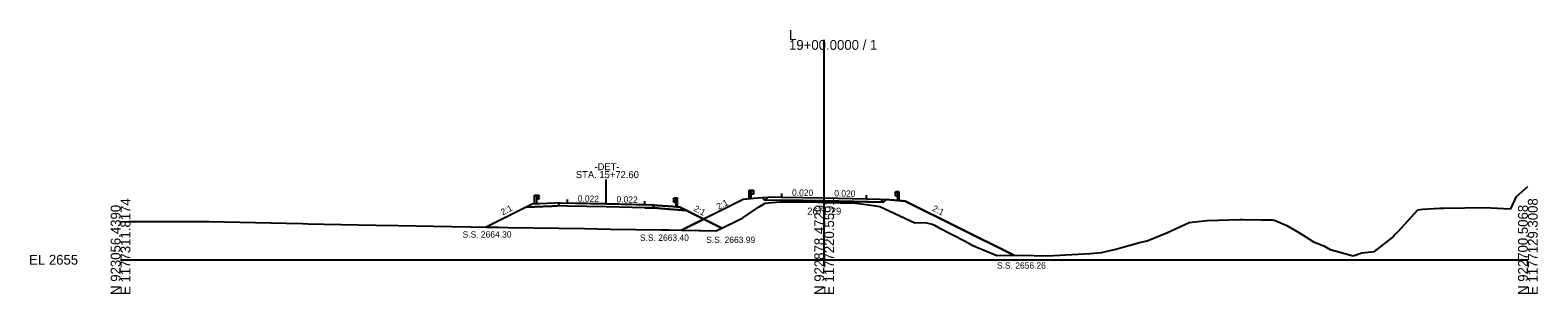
# Model space of a CAD drawing. Extents: x -26 to 1403, y -10 to 9563.
# Drawn here: x -25.7 to 402.8, y 8990.3 to 9065.3 of the extents above; entities that cross this region are included whole.
import ezdxf

# ---------------------------------------------------------------- set-up
doc = ezdxf.new("R2010")
doc.units = 0
for name, color, linetype in [('Exist Cross Section Cell', 7, 'Continuous'), ('Exist XS Center Line Elevation Label', 7, 'Continuous'), ('Exist XS Ground Line', 7, 'Continuous'), ('Prop XS Dump Level', 7, 'Continuous'), ('Prop XS Earthwork Shape', 7, 'Continuous'), ('Prop XS EOT Tick Mark', 7, 'Continuous'), ('Prop XS Finish Grade', 7, 'Continuous'), ('Prop XS Finish Grade Earthwork', 7, 'Continuous'), ('Prop XS Finish Grade Paved Shoulder', 7, 'Continuous'), ('Prop XS Finish Grade Pavement', 7, 'Continuous'), ('Prop XS Guardrail', 7, 'Continuous'), ('Prop XS Pvmt Edge Slope', 7, 'Continuous'), ('Prop XS SE Text', 7, 'Continuous'), ('Prop XS Shoulder Borrow Shape', 7, 'Continuous'), ('Prop XS Side Slope Text', 7, 'Continuous'), ('Prop XS SS Elevation Text', 7, 'Continuous'), ('Prop XS Subgrade Earthwork', 7, 'Continuous'), ('Prop XS Vertical Lines', 7, 'Continuous')]:
    doc.layers.add(name, color=color, linetype=linetype)

msp = doc.modelspace()

# ---------------------------------------------------------------- linework, layer by layer
at = {"layer": 'Exist Cross Section Cell'}
for p, q in [((200, 9000), (200, 9062.49)), ((0, 9000), (200, 9000)), ((200, 9000), (400, 9000))]:
    msp.add_line(p, q, dxfattribs=at)
at = {"layer": 'Exist XS Ground Line'}
for p, q in [((396.75, 9018.03), (400, 9020.83)), ((183.23, 9016.09), (187.42, 9016.46)), ((187.42, 9016.46), (187.88, 9016.46)), ((187.88, 9016.46), (198.23, 9016.34)), ((198.23, 9016.34), (200, 9016.29)), ((395.2, 9014.49), (396.75, 9018.03)), ((176.83, 9011.93), (181.34, 9014.91)), ((181.34, 9014.91), (183.23, 9016.09)), ((200, 9016.29), (208.98, 9016.08)), ((208.98, 9016.08), (209.49, 9016.07)), ((209.49, 9016.07), (209.85, 9016.03)), ((209.85, 9016.03), (213.89, 9015.39)), ((213.89, 9015.39), (215.77, 9015.1)), ((215.77, 9015.1), (225.72, 9010.54)), ((363.1, 9008.07), (368.74, 9014.2)), ((368.74, 9014.2), (370.13, 9014.34)), ((370.13, 9014.34), (374.96, 9014.69)), ((374.96, 9014.69), (376.25, 9014.69)), ((376.25, 9014.69), (387.91, 9014.87)), ((387.91, 9014.87), (393.12, 9014.62)), ((393.12, 9014.62), (395.2, 9014.49)), ((0, 9010.82), (2.35, 9010.84)), ((2.35, 9010.84), (25.16, 9010.84)), ((25.16, 9010.84), (47.07, 9010.38)), ((47.07, 9010.38), (51.76, 9010.29)), ((51.76, 9010.29), (53.28, 9010.25)), ((53.28, 9010.25), (57.87, 9010.15)), ((57.87, 9010.15), (72.53, 9009.82)), ((72.53, 9009.82), (78.97, 9009.77)), ((78.97, 9009.77), (88.99, 9009.54)), ((88.99, 9009.54), (104.69, 9009.29)), ((104.69, 9009.29), (107.42, 9009.25)), ((107.42, 9009.25), (110.11, 9009.19)), ((110.11, 9009.19), (131.88, 9008.86)), ((131.88, 9008.86), (139.35, 9008.72)), ((139.35, 9008.72), (153.53, 9008.52)), ((153.53, 9008.52), (154.29, 9008.49)), ((154.29, 9008.49), (155.91, 9008.47)), ((155.91, 9008.47), (169.32, 9008.2)), ((169.32, 9008.2), (174.98, 9010.98)), ((174.98, 9010.98), (176.83, 9011.93)), ((225.72, 9010.54), (228.63, 9010.62)), ((228.63, 9010.62), (230.3, 9010.21)), ((230.3, 9010.21), (230.67, 9010.13)), ((230.67, 9010.13), (231.34, 9009.81)), ((231.34, 9009.81), (232.49, 9009.17)), ((232.49, 9009.17), (240.07, 9005.26)), ((297.54, 9007.74), (303.71, 9010.63)), ((303.71, 9010.63), (308.86, 9011.15)), ((308.86, 9011.15), (318.09, 9011.47)), ((318.09, 9011.47), (318.56, 9011.47)), ((318.56, 9011.47), (319.13, 9011.47)), ((319.13, 9011.47), (324.12, 9011.38)), ((324.12, 9011.38), (327.32, 9011.32)), ((327.32, 9011.32), (327.78, 9011.28)), ((327.78, 9011.28), (328.18, 9011.19)), ((328.18, 9011.19), (331.48, 9009.7)), ((331.48, 9009.7), (334.47, 9008.05)), ((334.47, 9008.05), (336.1, 9006.95)), ((361.97, 9007.02), (363.1, 9008.07)), ((240.07, 9005.26), (242.29, 9004.02)), ((242.29, 9004.02), (244.01, 9003.28)), ((282.88, 9003.03), (289.64, 9004.95)), ((289.64, 9004.95), (291.76, 9005.39)), ((291.76, 9005.39), (297.54, 9007.74)), ((336.1, 9006.95), (339.06, 9005.12)), ((339.06, 9005.12), (341.97, 9004)), ((341.97, 9004), (343.8, 9002.94)), ((356.45, 9002.38), (361.52, 9006.3)), ((361.52, 9006.3), (361.97, 9007.02)), ((244.01, 9003.28), (244.96, 9002.94)), ((244.96, 9002.94), (249.04, 9001.21)), ((249.04, 9001.21), (255.75, 9001.28)), ((255.75, 9001.28), (263.45, 9001.09)), ((263.45, 9001.09), (275.58, 9001.77)), ((275.58, 9001.77), (278.78, 9002.06)), ((278.78, 9002.06), (282.88, 9003.03)), ((343.8, 9002.94), (350.31, 9001.14)), ((350.31, 9001.14), (352.82, 9001.96)), ((352.82, 9001.96), (356.45, 9002.38))]:
    msp.add_line(p, q, dxfattribs=at)
at = {"layer": 'Prop XS Dump Level'}
for p, q in [((188, 9017.81), (200, 9017.57)), ((200, 9017.57), (212, 9017.33)), ((125, 9016.15), (138, 9015.86)), ((138, 9015.86), (127, 9016.1)), ((149, 9015.62), (138, 9015.86)), ((138, 9015.86), (151, 9015.58))]:
    msp.add_line(p, q, dxfattribs=at)
at = {"layer": 'Prop XS Earthwork Shape'}
for p, q in [((177, 9017.17), (165.78, 9011.56)), ((182.43, 9017.6), (180, 9017.41)), ((183.15, 9016.88), (182.43, 9017.6)), ((188, 9016.97), (183.15, 9016.88)), ((183.23, 9016.09), (187.42, 9016.46)), ((187.42, 9016.46), (187.88, 9016.46)), ((187.88, 9016.46), (198.23, 9016.34)), ((200, 9016.73), (188, 9016.97)), ((198.23, 9016.34), (200, 9016.29)), ((200, 9016.29), (200, 9016.73)), ((216.85, 9016.4), (200, 9016.73)), ((200, 9016.73), (200, 9016.29)), ((217.57, 9017.12), (216.85, 9016.4)), ((220, 9016.93), (217.57, 9017.12)), ((220.82, 9016.86), (220, 9016.93)), ((253.86, 9001.26), (223, 9016.69)), ((115.3, 9014.99), (103.92, 9009.3)), ((122.61, 9015.27), (115.3, 9014.99)), ((124.18, 9015.33), (122.61, 9015.27)), ((127, 9015.27), (124.18, 9015.33)), ((138, 9015.03), (127, 9015.27)), ((149, 9014.79), (138, 9015.03)), ((151.85, 9014.73), (149, 9014.79)), ((153.43, 9014.6), (151.85, 9014.73)), ((160.87, 9014.01), (153.43, 9014.6)), ((165.78, 9011.56), (160.87, 9014.01)), ((176.83, 9011.93), (181.34, 9014.91)), ((181.34, 9014.91), (183.23, 9016.09)), ((200, 9016.29), (208.98, 9016.08)), ((208.98, 9016.08), (209.49, 9016.07)), ((209.49, 9016.07), (209.85, 9016.03)), ((209.85, 9016.03), (213.89, 9015.39)), ((213.89, 9015.39), (215.77, 9015.1)), ((215.77, 9015.1), (225.72, 9010.54)), ((103.92, 9009.3), (104.69, 9009.29)), ((104.69, 9009.29), (107.42, 9009.25)), ((107.42, 9009.25), (110.11, 9009.19)), ((110.11, 9009.19), (131.88, 9008.86)), ((131.88, 9008.86), (139.35, 9008.72)), ((139.35, 9008.72), (153.53, 9008.52)), ((153.53, 9008.52), (154.29, 9008.49)), ((154.29, 9008.49), (155.91, 9008.47)), ((155.91, 9008.47), (159.45, 9008.4)), ((159.45, 9008.4), (165.78, 9011.56)), ((165.78, 9011.56), (159.45, 9008.4)), ((165.78, 9011.56), (159.45, 9008.4)), ((159.45, 9008.4), (169.32, 9008.2)), ((159.45, 9008.4), (169.32, 9008.2)), ((170.92, 9008.98), (165.78, 9011.56)), ((170.92, 9008.98), (165.78, 9011.56)), ((165.78, 9011.56), (170.92, 9008.98)), ((169.32, 9008.2), (170.92, 9008.98)), ((169.32, 9008.2), (170.92, 9008.98)), ((170.92, 9008.98), (174.98, 9010.98)), ((174.98, 9010.98), (176.83, 9011.93)), ((225.72, 9010.54), (228.63, 9010.62)), ((228.63, 9010.62), (230.3, 9010.21)), ((230.3, 9010.21), (230.67, 9010.13)), ((230.67, 9010.13), (231.34, 9009.81)), ((231.34, 9009.81), (232.49, 9009.17)), ((232.49, 9009.17), (240.07, 9005.26)), ((240.07, 9005.26), (242.29, 9004.02)), ((242.29, 9004.02), (244.01, 9003.28)), ((244.01, 9003.28), (244.96, 9002.94)), ((244.96, 9002.94), (249.04, 9001.21)), ((249.04, 9001.21), (253.86, 9001.26))]:
    msp.add_line(p, q, dxfattribs=at)
for points in [[(180, 9017.41), (179.18, 9017.34), (178.68, 9017.3), (177, 9017.17)], [(223, 9016.69), (221.32, 9016.82), (220.82, 9016.86)]]:
    msp.add_lwpolyline(points, dxfattribs=at)
at = {"layer": 'Prop XS EOT Tick Mark'}
for p, q in [((127, 9016.1), (127, 9017.1)), ((149, 9015.62), (149, 9016.62)), ((188, 9017.81), (188, 9018.81)), ((212, 9017.33), (212, 9018.33))]:
    msp.add_line(p, q, dxfattribs=at)
at = {"layer": 'Prop XS Finish Grade'}
for p, q in [((184, 9017.73), (182.43, 9017.6)), ((216, 9017.25), (217.57, 9017.12)), ((125, 9016.15), (123.43, 9016.09)), ((151, 9015.58), (152.58, 9015.46))]:
    msp.add_line(p, q, dxfattribs=at)
at = {"layer": 'Prop XS Finish Grade Earthwork'}
for p, q in [((177, 9017.17), (159.45, 9008.4)), ((180, 9017.41), (177, 9017.17)), ((182.43, 9017.6), (180, 9017.41)), ((217.57, 9017.12), (220, 9016.93)), ((220, 9016.93), (223, 9016.69)), ((223, 9016.69), (253.86, 9001.26)), ((115.3, 9014.99), (103.92, 9009.3)), ((117, 9015.84), (115.3, 9014.99)), ((119, 9015.92), (117, 9015.84)), ((123.43, 9016.09), (119, 9015.92)), ((152.58, 9015.46), (157.01, 9015.1)), ((157.01, 9015.1), (159.01, 9014.94)), ((159.01, 9014.94), (160.87, 9014.01)), ((160.87, 9014.01), (170.92, 9008.98))]:
    msp.add_line(p, q, dxfattribs=at)
at = {"layer": 'Prop XS Finish Grade Paved Shoulder'}
for p, q in [((188, 9017.81), (184, 9017.73)), ((212, 9017.33), (216, 9017.25))]:
    msp.add_line(p, q, dxfattribs=at)
at = {"layer": 'Prop XS Finish Grade Pavement'}
for p, q in [((188, 9017.81), (200, 9017.57)), ((200, 9017.57), (212, 9017.33)), ((125, 9016.15), (138, 9015.86)), ((138, 9015.86), (151, 9015.58))]:
    msp.add_line(p, q, dxfattribs=at)
at = {"layer": 'Prop XS Guardrail'}
for p, q in [((117.68, 9018.37), (118.18, 9018.37)), ((117.68, 9015.87), (117.68, 9018.37)), ((118.18, 9018.37), (118.68, 9018.37)), ((118.18, 9018.37), (118.18, 9015.87)), ((118.68, 9017.23), (118.18, 9017.23)), ((118.68, 9018.37), (118.97, 9018.17)), ((118.97, 9018.05), (118.68, 9017.85)), ((118.68, 9017.85), (118.68, 9017.75)), ((118.68, 9017.75), (118.97, 9017.55)), ((118.97, 9017.43), (118.68, 9017.23)), ((118.97, 9018.17), (119, 9018.11)), ((119, 9018.11), (118.97, 9018.05)), ((118.97, 9017.55), (119, 9017.49)), ((119, 9017.49), (118.97, 9017.43)), ((157.03, 9017.3), (157, 9017.24)), ((157, 9017.24), (157.03, 9017.18)), ((157.03, 9016.68), (157, 9016.62)), ((157, 9016.62), (157.03, 9016.56)), ((157.32, 9017.5), (157.03, 9017.3)), ((157.03, 9017.18), (157.32, 9016.98)), ((157.32, 9016.88), (157.03, 9016.68)), ((157.03, 9016.56), (157.32, 9016.36)), ((157.82, 9017.5), (157.32, 9017.5)), ((157.32, 9016.98), (157.32, 9016.88)), ((157.32, 9016.36), (157.82, 9016.36)), ((158.32, 9017.5), (157.82, 9017.5)), ((157.82, 9017.5), (157.82, 9015)), ((158.32, 9015), (158.32, 9017.5)), ((178.68, 9019.8), (179.18, 9019.8)), ((178.68, 9017.3), (178.68, 9019.8)), ((179.18, 9019.8), (179.68, 9019.8)), ((179.18, 9019.8), (179.18, 9017.3)), ((179.68, 9018.67), (179.18, 9018.67)), ((179.68, 9019.8), (179.97, 9019.6)), ((179.97, 9019.48), (179.68, 9019.28)), ((179.68, 9019.28), (179.68, 9019.19)), ((179.68, 9019.19), (179.97, 9018.99)), ((179.97, 9018.87), (179.68, 9018.67)), ((179.97, 9019.6), (180, 9019.54)), ((180, 9019.54), (179.97, 9019.48)), ((179.97, 9018.99), (180, 9018.93)), ((180, 9018.93), (179.97, 9018.87)), ((220.03, 9019.12), (220, 9019.06)), ((220, 9019.06), (220.03, 9019)), ((220.03, 9018.51), (220, 9018.45)), ((220, 9018.45), (220.03, 9018.39)), ((220.32, 9019.32), (220.03, 9019.12)), ((220.03, 9019), (220.32, 9018.8)), ((220.32, 9018.71), (220.03, 9018.51)), ((220.03, 9018.39), (220.32, 9018.19)), ((220.82, 9019.32), (220.32, 9019.32)), ((220.32, 9018.8), (220.32, 9018.71)), ((220.32, 9018.19), (220.82, 9018.19)), ((221.32, 9019.32), (220.82, 9019.32)), ((220.82, 9019.32), (220.82, 9016.82)), ((221.32, 9016.82), (221.32, 9019.32))]:
    msp.add_line(p, q, dxfattribs=at)
at = {"layer": 'Prop XS Pvmt Edge Slope'}
for p, q in [((184, 9017.73), (183.15, 9016.88)), ((216, 9017.25), (216.85, 9016.4)), ((125, 9016.15), (124.18, 9015.33)), ((151, 9015.58), (151.85, 9014.73))]:
    msp.add_line(p, q, dxfattribs=at)
at = {"layer": 'Prop XS Shoulder Borrow Shape'}
for p, q in [((117, 9015.84), (115.3, 9014.99)), ((115.3, 9014.99), (122.61, 9015.27)), ((117.68, 9015.87), (117, 9015.84)), ((123.43, 9016.09), (119, 9015.92)), ((122.61, 9015.27), (124.18, 9015.33)), ((125, 9016.15), (123.43, 9016.09)), ((124.18, 9015.33), (125, 9016.15)), ((152.58, 9015.46), (151, 9015.58)), ((151, 9015.58), (151.85, 9014.73)), ((151.85, 9014.73), (153.43, 9014.6)), ((157.01, 9015.1), (152.58, 9015.46)), ((153.43, 9014.6), (160.87, 9014.01)), ((157.82, 9015.04), (157.01, 9015.1)), ((158.32, 9015), (157.82, 9015.04)), ((159.01, 9014.94), (158.32, 9015)), ((158.32, 9015), (158.32, 9015)), ((160.87, 9014.01), (159.01, 9014.94))]:
    msp.add_line(p, q, dxfattribs=at)
for points in [[(119, 9015.92), (118.18, 9015.88), (117.68, 9015.87)], [(158.32, 9015), (158.32, 9015)]]:
    msp.add_lwpolyline(points, dxfattribs=at)
at = {"layer": 'Prop XS Subgrade Earthwork'}
for p, q in [((183.15, 9016.88), (182.43, 9017.6)), ((188, 9016.97), (183.15, 9016.88)), ((188, 9016.96), (188, 9016.97)), ((188, 9016.97), (216.85, 9016.4)), ((216.85, 9016.4), (217.57, 9017.12)), ((122.61, 9015.27), (115.3, 9014.99)), ((124.18, 9015.33), (122.61, 9015.27)), ((127, 9015.27), (124.18, 9015.33)), ((138, 9015.03), (127, 9015.27)), ((149, 9014.79), (138, 9015.03)), ((149, 9014.79), (151.85, 9014.73)), ((151.85, 9014.73), (153.43, 9014.6)), ((153.43, 9014.6), (160.87, 9014.01))]:
    msp.add_line(p, q, dxfattribs=at)
at = {"layer": 'Prop XS Vertical Lines'}
msp.add_line((138, 9015.86), (138, 9022.86), dxfattribs=at)

# ---------------------------------------------------------------- texts
at = {"layer": 'Exist Cross Section Cell'}
for s, p in [('L', (190, 9062.49)), ('19+00.0000 / 1', (190, 9059.69)), ('EL 2655', (-26, 8998.6))]:
    msp.add_text(s, height=2.8, dxfattribs=at).set_placement(p)
for s, p in [('E 1177311.8174', (2.8, 8990)), ('E 1177220.5591', (202.8, 8990)), ('E 1177129.3008', (402.8, 8990)), ('N 923056.4390', (0, 8990)), ('N 922878.4729', (200, 8990)), ('N 922700.5068', (400, 8990))]:
    msp.add_text(s, height=2.8, rotation=90, dxfattribs=at).set_placement(p)
at = {"layer": 'Exist XS Center Line Elevation Label'}
msp.add_text('2671.29', height=2, dxfattribs=at).set_placement((195.18, 9012.83))
at = {"layer": 'Prop XS Dump Level'}
for s, p in [('Case2', (180, 9017.37)), ('Case2', (220, 9016.89)), ('Case1', (119, 9015.76)), ('Case1', (157, 9015.06))]:
    msp.add_text(s, height=0.04, dxfattribs=at).set_placement(p)
at = {"layer": 'Prop XS SE Text'}
for s, rotation, p in [('0.022', 358.756, (129.95, 9016.54)), ('0.022', 358.756, (140.95, 9016.3)), ('0.020', 358.8542, (190.84, 9018.25)), ('0.020', 358.8542, (202.84, 9018.01))]:
    msp.add_text(s, height=1.8, rotation=rotation, dxfattribs=at).set_placement(p)
at = {"layer": 'Prop XS Side Slope Text'}
for rotation, p in [(26.5651, (169.93, 9014.17)), (26.5651, (108.61, 9012.6)), (331.8429, (162.71, 9014.01)), (333.4349, (230.54, 9014))]:
    msp.add_text('2:1', height=1.8, rotation=rotation, dxfattribs=at).set_placement(p)
at = {"layer": 'Prop XS SS Elevation Text'}
for s, p in [('S.S. 2664.30', (97.21, 9006.31)), ('S.S. 2663.40', (147.62, 9005.38)), ('S.S. 2663.99', (166.46, 9004.76)), ('S.S. 2656.26', (249.09, 8997.47))]:
    msp.add_text(s, height=1.8, dxfattribs=at).set_placement(p)
at = {"layer": 'Prop XS Vertical Lines'}
for s, p in [('STA. 15+72.60', (129.42, 9023.21)), ('-DET-', (134.7, 9025.46))]:
    msp.add_text(s, height=2, dxfattribs=at).set_placement(p)

doc.saveas('drawing.dxf')
